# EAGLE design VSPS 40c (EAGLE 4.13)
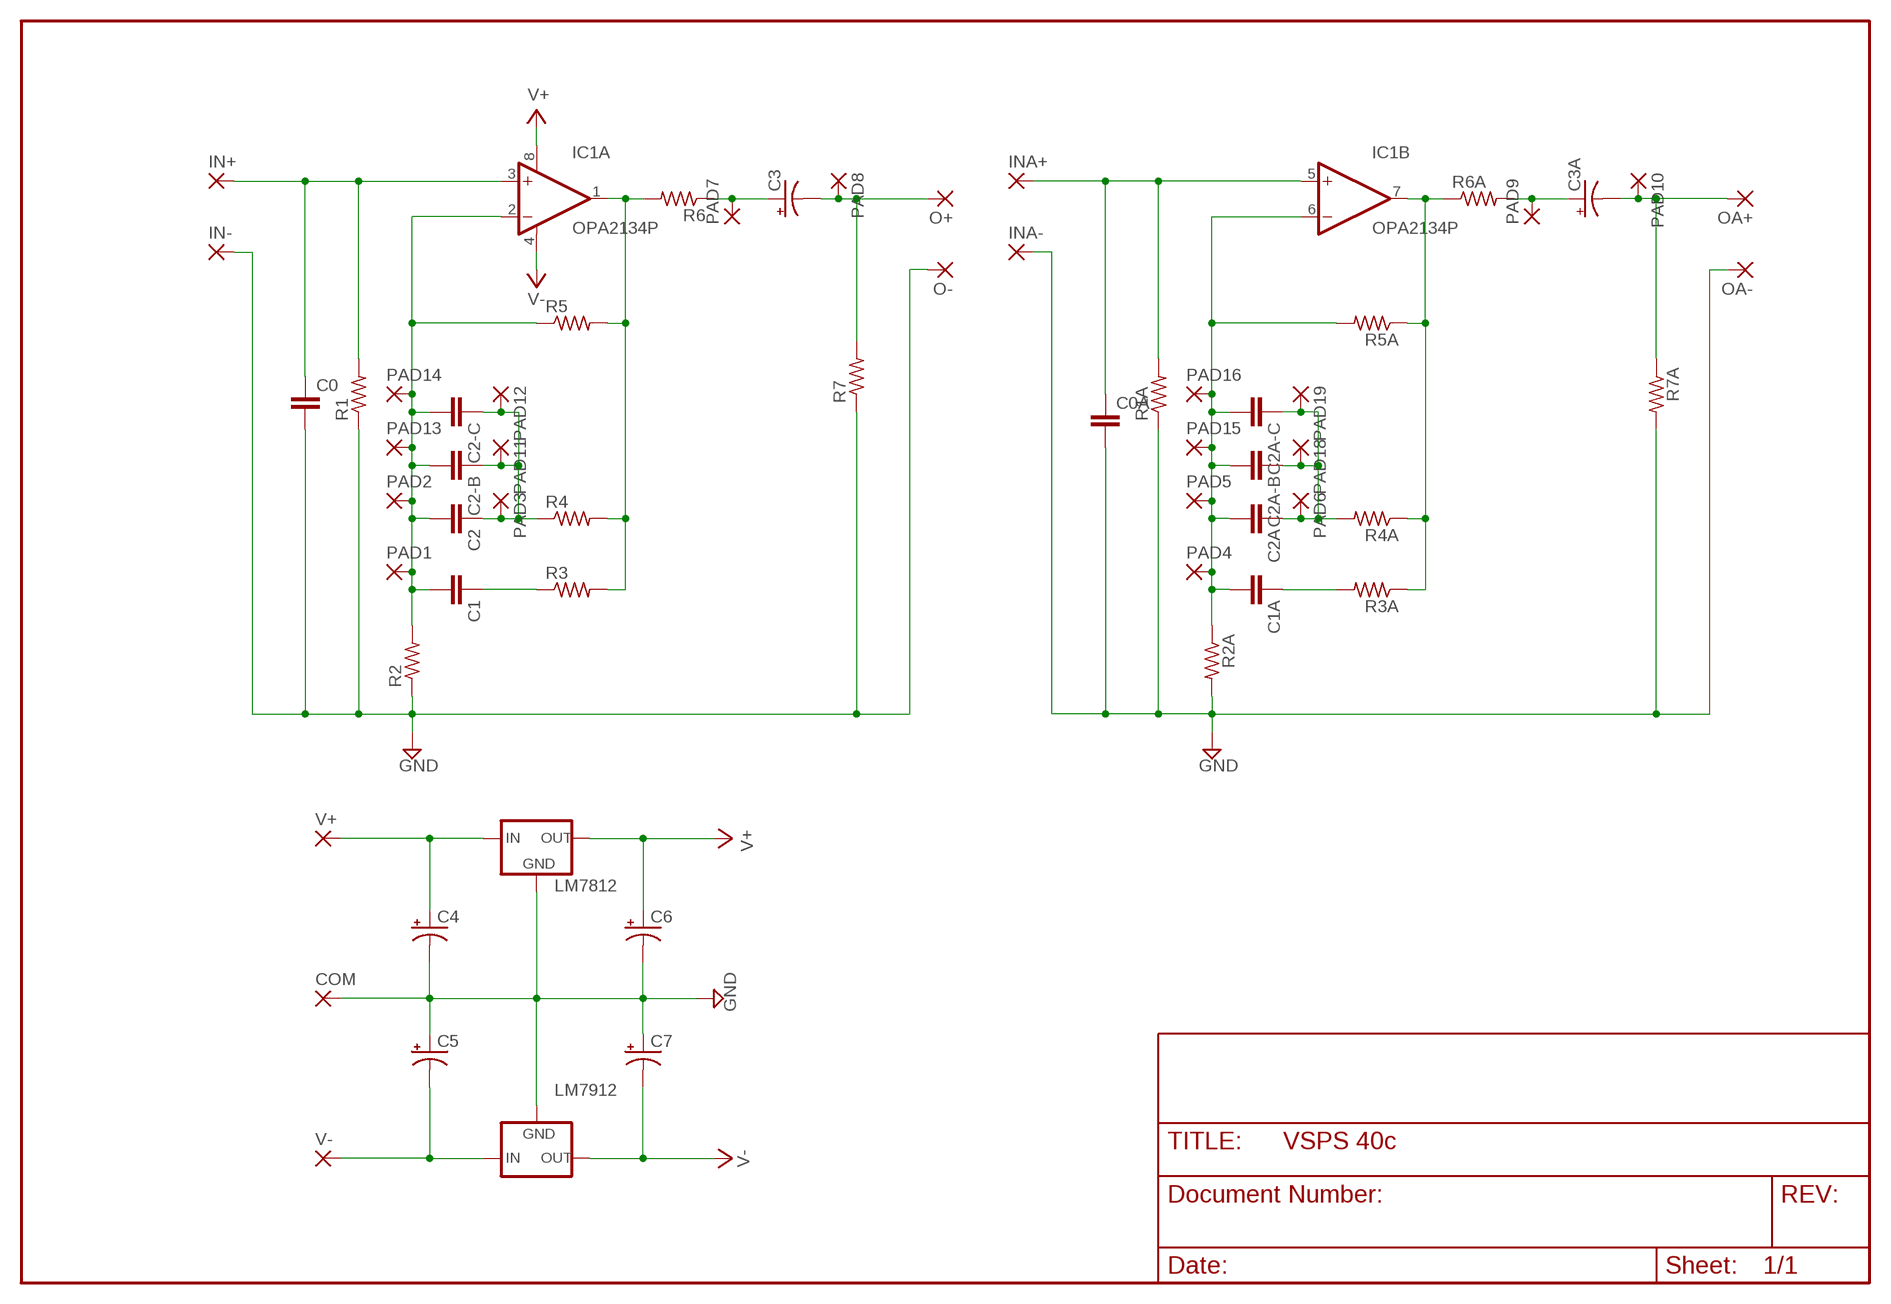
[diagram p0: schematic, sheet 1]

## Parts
C0  C-EU025-025X050  [C025-025X050]
C0A  C-EU025-025X050  [C025-025X050]
C1  C-EU050-025X075-SS  [C050-025X075-SS]
C1A  C-EU050-025X075-SS  [C050-025X075-SS]
C2  C-EU050-025X075-SS  [C050-025X075-SS]
C2-B  C-EU050-025X075-SS  [C050-025X075-SS]
C2-C  C-EU050-025X075-SS  [C050-025X075-SS]
C2A  C-EU050-025X075-SS  [C050-025X075-SS]
C2A-B  C-EU050-025X075-SS  [C050-025X075-SS]
C2A-C  C-EU050-025X075-SS  [C050-025X075-SS]
C3  CPOL-USE2-4  [E2-4]
C3A  CPOL-USE2-4  [E2-4]
C4  CPOL-USE5-13  [E5-13]
C5  CPOL-USE5-13  [E5-13]
C6  CPOL-USE3.5-8  [E3,5-8]
C7  CPOL-USE3.5-8  [E3,5-8]
COM  2,54/1,0  [2,54/1,0]
IC1  OPA2134P  [DIL08]
IN+  2,54/1,0  [2,54/1,0]
IN-  2,54/1,0  [2,54/1,0]
INA+  2,54/1,0  [2,54/1,0]
INA-  2,54/1,0  [2,54/1,0]
LM7812  78XXS  [78XXS]
LM7912  79XXS  [79XXS]
O+  2,54/1,0  [2,54/1,0]
O-  2,54/1,0  [2,54/1,0]
OA+  2,54/1,0  [2,54/1,0]
OA-  2,54/1,0  [2,54/1,0]
PAD1  1,6/0,9-SS  [1,6/0,9-SS]
PAD2  1,6/0,9-SS  [1,6/0,9-SS]
PAD3  1,6/0,9-SS  [1,6/0,9-SS]
PAD4  1,6/0,9-SS  [1,6/0,9-SS]
PAD5  1,6/0,9-SS  [1,6/0,9-SS]
PAD6  1,6/0,9-SS  [1,6/0,9-SS]
PAD7  1,6/0,9-SS  [1,6/0,9-SS]
PAD8  1,6/0,9-SS  [1,6/0,9-SS]
PAD9  1,6/0,9-SS  [1,6/0,9-SS]
PAD10  1,6/0,9-SS  [1,6/0,9-SS]
PAD11  1,6/0,9-SS  [1,6/0,9-SS]
PAD12  1,6/0,9-SS  [1,6/0,9-SS]
PAD13  1,6/0,9-SS  [1,6/0,9-SS]
PAD14  1,6/0,9-SS  [1,6/0,9-SS]
PAD15  1,6/0,9-SS  [1,6/0,9-SS]
PAD16  1,6/0,9-SS  [1,6/0,9-SS]
PAD18  1,6/0,9-SS  [1,6/0,9-SS]
PAD19  1,6/0,9-SS  [1,6/0,9-SS]
R1  R-US_0207/10-SS  [0207/10-SS]
R1A  R-US_0207/10-SS  [0207/10-SS]
R2  R-US_0207/10-SS  [0207/10-SS]
R2A  R-US_0207/10-SS  [0207/10-SS]
R3  R-US_0207/10-SS  [0207/10-SS]
R3A  R-US_0207/10-SS  [0207/10-SS]
R4  R-US_0207/10-SS  [0207/10-SS]
R4A  R-US_0207/10-SS  [0207/10-SS]
R5  R-US_0207/10-SS  [0207/10-SS]
R5A  R-US_0207/10-SS  [0207/10-SS]
R6  R-US_0207/10-SS  [0207/10-SS]
R6A  R-US_0207/10-SS  [0207/10-SS]
R7  R-US_0207/10-SS  [0207/10-SS]
R7A  R-US_0207/10-SS  [0207/10-SS]
V+  2,54/1,0  [2,54/1,0]
V-  2,54/1,0  [2,54/1,0]

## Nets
GND: C0.2 C0A.2 C4.- C5.+ C6.- C7.+ COM.1(P) IN-.1(P) INA-.1(P) LM7812.GND LM7912.GND O-.1(P) OA-.1(P) R1.1 R1A.1 R2.1 R2A.2 R7.1 R7A.2
N$1: C0.1 IC1.3(A:+IN) IN+.1(P) R1.2
N$3: IC1.1(A:OUT) R3.2 R4.2 R5.2 R6.2
N$7: C0A.1 IC1.5(B:+IN) INA+.1(P) R1A.2
N$8: C3A.- OA+.1(P) PAD10.1(P) R7A.1
N$9: C3A.+ PAD9.1(P) R6A.2
N$10: IC1.7(B:OUT) R3A.1 R4A.1 R5A.1 R6A.1
N$12: C1.1 R3.1
N$13: C1A.1 R3A.2
N$17: C3.+ PAD7.1(P) R6.1
N$18: C3.- O+.1(P) PAD8.1(P) R7.2
RIAA-1: C1.2 C2-B.2 C2-C.2 C2.2 IC1.2(A:-IN) PAD1.1(P) PAD2.1(P) PAD13.1(P) PAD14.1(P) R2.2 R5.1
RIAA-1A: C1A.2 C2A-B.2 C2A-C.2 C2A.2 IC1.6(B:-IN) PAD4.1(P) PAD5.1(P) PAD15.1(P) PAD16.1(P) R2A.1 R5A.2
RIAA-2: C2-B.1 C2-C.1 C2.1 PAD3.1(P) PAD11.1(P) PAD12.1(P) R4.1
RIAA-2A: C2A-B.1 C2A-C.1 C2A.1 PAD6.1(P) PAD18.1(P) PAD19.1(P) R4A.2
V+: C6.+ IC1.8(A:V+) LM7812.OUT
V+IN: C4.+ LM7812.IN V+.1(P)
V-: C7.- IC1.4(A:V-) LM7912.OUT
V-IN: C5.- LM7912.IN V-.1(P)

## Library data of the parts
C0 C0A C1 C1A C2 C2-B C2-C C2A C2A-B C2A-C = rcl:C-EU: CAPACITOR, European symbol
C3 C3A C4-C7 = rcl:CPOL-US: POLARIZED CAPACITOR, American symbol
COM IN+ IN- INA+ INA- O+ O- OA+ OA- V+ V- = wirepad:2,54/1,0: THROUGH-HOLE PAD
IC1 = burr-brown:OPA2134: Operational Amplifier
LM7812 = v-reg:78XXS: VOLTAGE REGULATOR
LM7912 = v-reg:79XXS: VOLTAGE REGULATOR
PAD1-PAD16 PAD18 PAD19 = wirepad:1,6/0,9-SS: Through hole pad
R1 R1A R2 R2A R3 R3A R4 R4A R5 R5A R6 R6A R7 R7A = rcl:R-US_: RESISTOR, American symbol

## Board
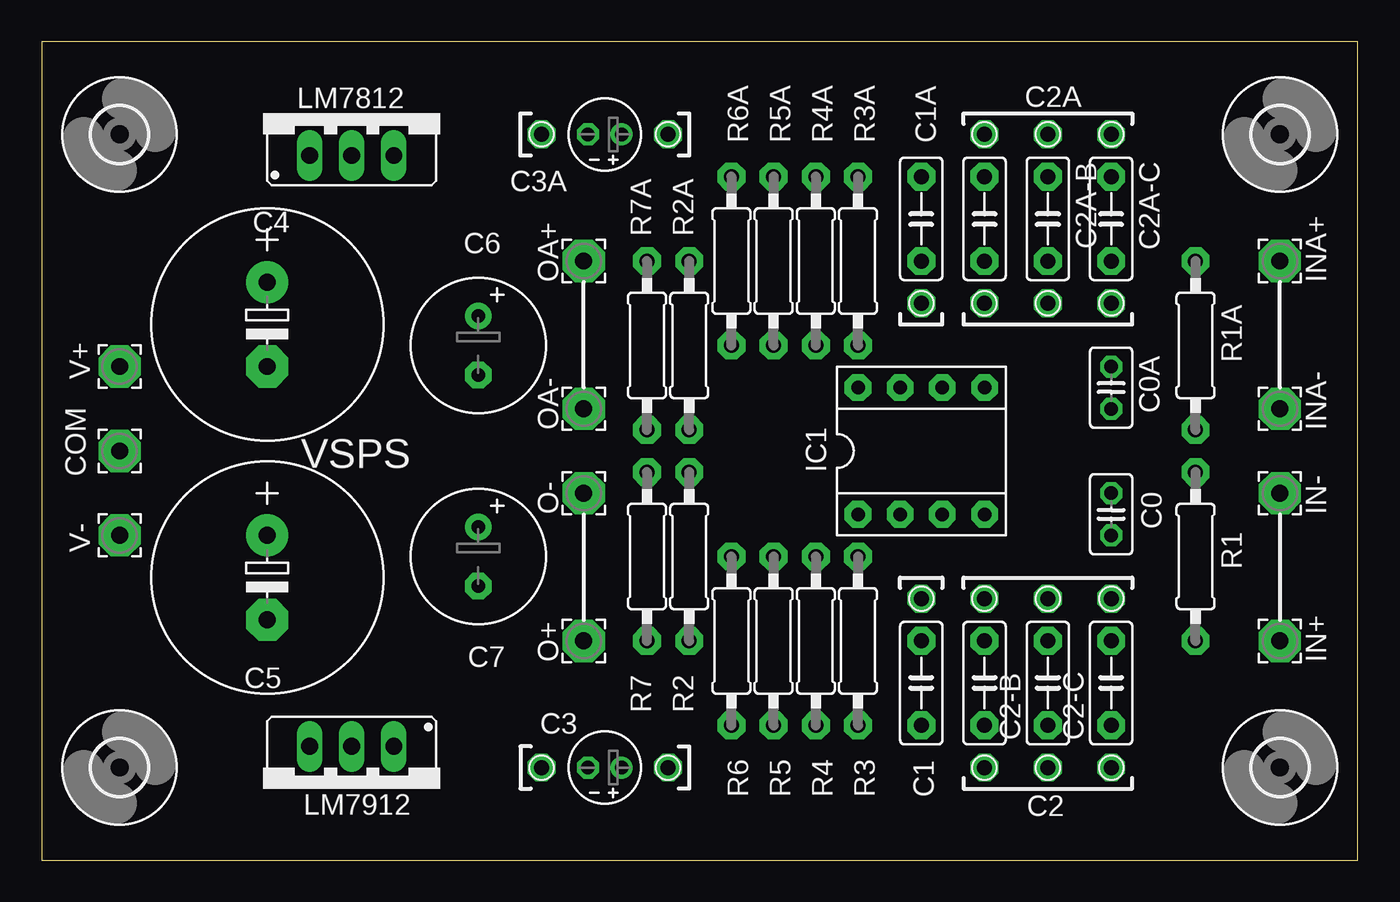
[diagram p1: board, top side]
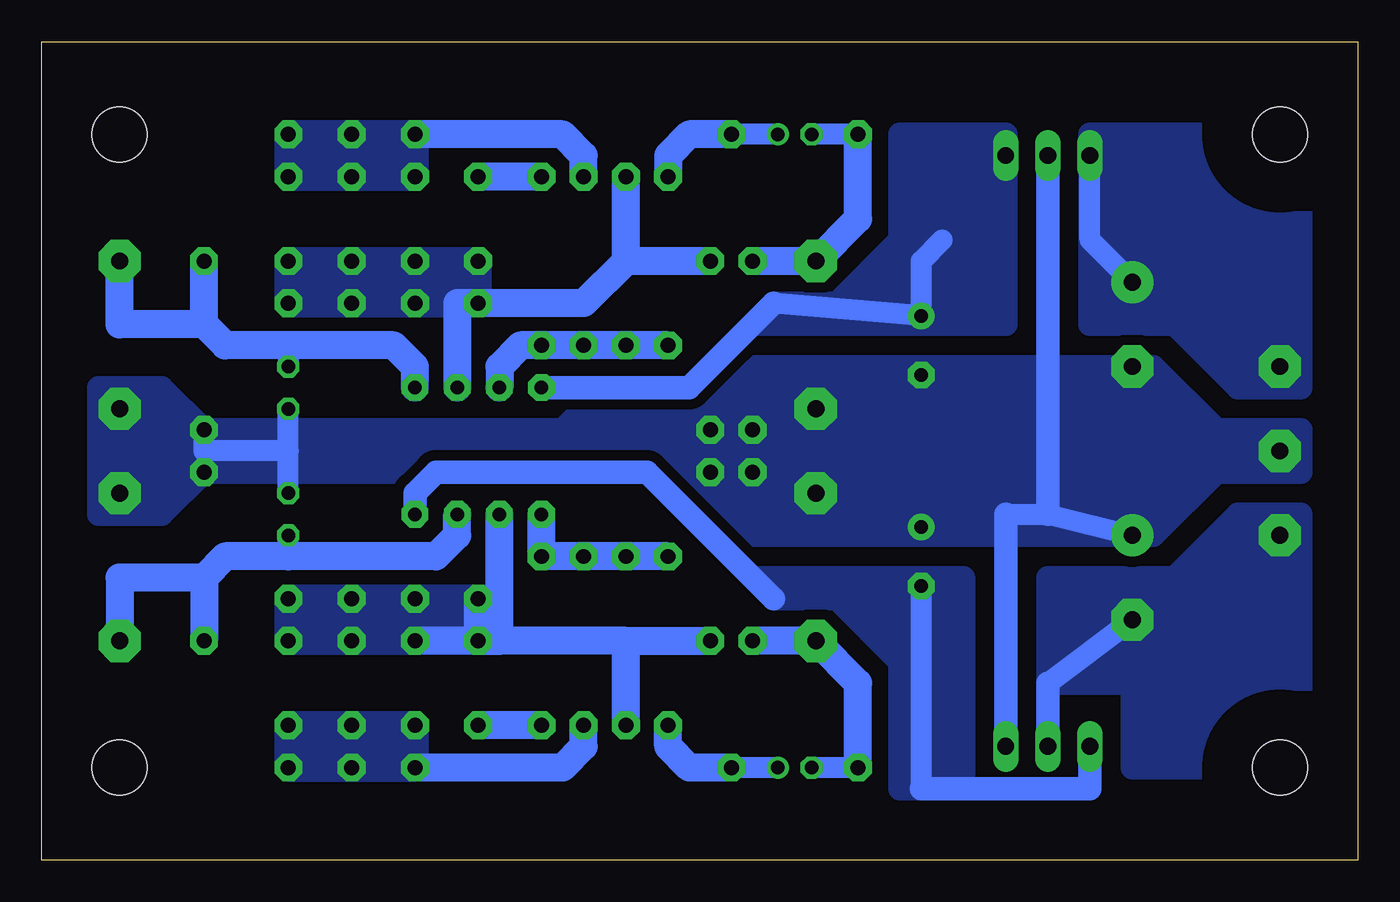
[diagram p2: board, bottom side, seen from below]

Size 79.25 x 49.28 mm. Coordinates in mm from the lower left corner, seen from the top.
Outline: 0,0 79.25,0 79.25,49.28 0,49.28 0,0
Copper layers (1*16): Top 0.035mm / dielectric 1.5mm / Bottom 0.035mm
Design rules "10mils": minimum track width 10mil, minimum drill 24mil, track to track 10mil, track to pad 10mil, pad to pad 10mil, via to via 10mil, smd to smd 10mil, copper to edge 40mil, drill to drill 10mil, minimum pad ring 10mil, minimum via ring 8mil, stop-mask expansion 0mil, vias tented up to drill 0mil, thermal gap 10mil

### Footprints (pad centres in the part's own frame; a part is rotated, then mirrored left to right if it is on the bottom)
C025-025X050 = drill 0.813 octagon: 1 -1.27,0; 2 1.27,0
C050-025X075-SS = drill 0.9 pad 1.676 octagon: 1 -2.54,0; 2 2.54,0
E2-4 = drill 0.813 pad 1.27 round: + -1.016,0 | drill 0.813 pad 1.27 octagon: - 1.016,0
E5-13 = drill 1.016 pad 2.54 round: + -2.54,0 | drill 1.016 pad 2.54 octagon: - 2.54,0
E3,5-8 = drill 0.813 pad 1.6 round: + -1.778,0 | drill 0.813 pad 1.6 octagon: - 1.778,0
2,54/1,0 = drill 1.016 pad 2.54 octagon: 1 0,0
DIL08 = drill 0.813 pad 1.6 octagon: 1 -3.81,-3.81; 2 -1.27,-3.81; 3 1.27,-3.81; 4 3.81,-3.81; 5 3.81,3.81; 6 1.27,3.81; 7 -1.27,3.81; 8 -3.81,3.81
78XXS = drill 1.016 long: GND 0,-2.54; IN -2.54,-2.54; OUT 2.54,-2.54
79XXS = drill 1.016 long: GND -2.54,-2.54; IN 0,-2.54; OUT 2.54,-2.54
1,6/0,9-SS = drill 0.9 pad 1.676 octagon: 1 0,0
0207/10-SS = drill 0.9 pad 1.676 octagon: 1 -5.08,0; 2 5.08,0
3,3 = hole 3.3: 0,0

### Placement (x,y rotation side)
C0  64.39,20.83 90 top
C0A  64.39,28.45 270 top
C1  52.96,10.67 90 top
C1A  52.96,38.61 270 top
C2  56.77,10.67 90 top
C2-B  60.58,10.67 90 top
C2-C  64.39,10.67 90 top
C2A  56.77,38.61 270 top
C2A-B  60.58,38.61 270 top
C2A-C  64.39,38.61 270 top
C3  33.91,5.59 180 top
C3A  33.91,43.69 180 top
C4  13.59,32.26 270 top
C5  13.59,17.02 270 top
C6  26.29,30.99 270 top
C7  26.29,18.29 270 top
COM  4.7,24.64 0 top
IC1  52.96,24.64 0 top
IN+  74.55,13.21 0 top
IN-  74.55,22.1 0 top
INA+  74.55,36.07 0 top
INA-  74.55,27.18 0 top
LM7812  18.67,44.96 0 top
LM7912  18.67,4.32 180 top
O+  32.64,13.21 0 top
O-  32.64,22.1 0 top
OA+  32.64,36.07 0 top
OA-  32.64,27.18 0 top
PAD1  52.96,15.75 0 top
PAD2  60.58,15.75 0 top
PAD3  56.77,5.59 0 top
PAD4  52.96,33.53 0 top
PAD5  56.77,33.53 0 top
PAD6  56.77,43.69 0 top
PAD7  37.72,5.59 0 top
PAD8  30.1,5.59 0 top
PAD9  37.72,43.69 0 top
PAD10  30.1,43.69 0 top
PAD11  64.39,5.59 0 top
PAD12  60.58,5.59 0 top
PAD13  64.39,15.75 0 top
PAD14  56.77,15.75 0 top
PAD15  64.39,33.53 0 top
PAD16  60.58,33.53 0 top
PAD18  64.39,43.69 0 top
PAD19  60.58,43.69 0 top
R1  69.47,18.29 270 top
R1A  69.47,30.99 90 top
R2  38.99,18.29 270 top
R2A  38.99,30.99 270 top
R3  49.15,13.21 90 top
R3A  49.15,36.07 90 top
R4  46.61,13.21 90 top
R4A  46.61,36.07 90 top
R5  44.07,13.21 90 top
R5A  44.07,36.07 90 top
R6  41.53,13.21 90 top
R6A  41.53,36.07 90 top
R7  36.45,18.29 270 top
R7A  36.45,30.99 270 top
U$1  [3,3]  4.7,43.69 0 top
U$2  [3,3]  74.55,43.69 0 top
U$3  [3,3]  74.55,5.59 0 top
U$4  [3,3]  4.7,5.59 0 top
V+  4.7,29.72 0 top
V-  4.7,19.56 0 top

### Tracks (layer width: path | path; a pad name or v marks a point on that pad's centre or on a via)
GND
  Bottom 1.27: 21.21,20.83 18.67,20.83 C5.+ | 64.39,24.64 C0A.2 | C0.2 64.39,24.64 | 64.39,24.64 69.47,24.64 R1A.1
  Bottom 1.422: 18.67,20.83 LM7812.GND | LM7912.GND 21.21,20.83
  pour Bottom (isolate 0.61, no thermals): 12.32,19.56 8.51,23.37 3.43,23.37 3.43,25.91 8.51,25.91 12.32,29.72 38.99,29.72 41.53,27.18 46.61,27.18 47.88,25.91 69.47,25.91 72.01,28.45 75.82,28.45 75.82,20.83 72.01,20.83 69.47,23.37 42.8,23.37 38.99,19.56
N$1
  Bottom 1.27: 64.39,18.29 C0.1
  Bottom 1.676: IC1.3 54.23,19.56 55.5,18.29 64.39,18.29 68.2,18.29 69.47,17.02 | 69.47,17.02 R1.2 | IN+.1 74.55,17.02 69.47,17.02
N$3
  Bottom 1.676: IC1.1 R3.2 R4.2 R5.2 R6.2
N$7
  Bottom 1.27: 64.39,30.99 C0A.1
  Bottom 1.676: 69.47,32.26 68.2,30.99 64.39,30.99 58.04,30.99 56.77,29.72 IC1.5 | 69.47,32.26 R1A.2 | INA+.1 74.55,32.26 69.47,32.26
N$8
  Bottom 1.27: PAD10.1 C3A.-
  Bottom 1.676: R7A.1 OA+.1 30.1,38.61 PAD10.1
N$9
  Bottom 1.27: C3A.+ PAD9.1
  Bottom 1.676: PAD9.1 40.26,43.69 41.53,42.42 R6A.2
N$10
  Bottom 1.676: IC1.7 51.69,29.72 50.42,30.99 R3A.1 R4A.1 R5A.1 R6A.1
N$12
  Bottom 1.676: R3.1 C1.1
N$13
  Bottom 1.676: R3A.2 C1A.1
N$17
  Bottom 1.27: C3.+ PAD7.1
  Bottom 1.676: PAD7.1 40.26,5.59 41.53,6.86 R6.1
N$18
  Bottom 1.27: PAD8.1 C3.-
  Bottom 1.676: R7.2 O+.1 30.1,10.67 PAD8.1
RIAA-1
  Bottom 1.676: 44.07,13.21 R2.2 | R5.1 44.07,13.21 | C1.2 51.69,13.21 IC1.2 | 44.07,13.21 C1.2 | C1.2 C2.2 | C1.2 PAD1.1
  pour Bottom (no thermals): 51.69,13.21 51.69,15.75 64.39,15.75 64.39,13.21
RIAA-1A
  Bottom 1.676: 44.07,36.07 R5A.2 | R2A.1 44.07,36.07 | 44.07,36.07 46.61,33.53 PAD4.1 54.23,33.53 IC1.6
  pour Bottom (no thermals): 52.96,33.53 52.96,36.07 64.39,36.07 64.39,33.53
RIAA-2
  Bottom 1.676: R4.1 46.61,6.86 47.88,5.59 PAD3.1
  pour Bottom (no thermals): 56.77,5.59 56.77,8.13 64.39,8.13 64.39,5.59
RIAA-2A
  Bottom 1.676: R4A.2 46.61,42.42 47.88,43.69 PAD6.1
  pour Bottom (no thermals): 56.77,41.15 56.77,43.69 64.39,43.69 64.39,41.15
V+
  Bottom 1.27: 35.18,33.53 C6.+ 26.29,36.07 25.02,37.34
  Bottom 1.422: 35.18,33.53 40.26,28.45 IC1.8
  pour Bottom (isolate 0.61, no thermals): 21.21,43.69 21.21,32.26 36.45,32.26 35.18,33.53 31.37,33.53 27.56,37.34 27.56,43.69
V+IN
  Bottom 1.27: LM7812.IN 16.13,37.34 C4.+
  pour Bottom (isolate 0.61, no thermals): 3.43,28.45 7.24,28.45 11.05,32.26 16.13,32.26 16.13,43.69 3.43,43.69
V-
  Bottom 1.27: 26.29,4.32 C7.-
  Bottom 1.422: 35.18,15.75 42.8,23.37 55.5,23.37 56.77,22.1 IC1.4 | LM7912.OUT 16.13,4.32 26.29,4.32
  pour Bottom (isolate 0.61, no thermals): 23.75,4.32 23.75,17.02 36.45,17.02 35.18,15.75 31.37,15.75 27.56,11.94 27.56,4.32
V-IN
  Bottom 1.27: 18.67,10.67 C5.-
  Bottom 1.422: LM7912.IN 18.67,10.67
  pour Bottom (isolate 0.61, no thermals): 3.43,20.83 7.24,20.83 11.05,17.02 18.67,17.02 18.67,10.67 13.59,10.67 13.59,5.59 3.43,5.59

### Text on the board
tPlace: VSPS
